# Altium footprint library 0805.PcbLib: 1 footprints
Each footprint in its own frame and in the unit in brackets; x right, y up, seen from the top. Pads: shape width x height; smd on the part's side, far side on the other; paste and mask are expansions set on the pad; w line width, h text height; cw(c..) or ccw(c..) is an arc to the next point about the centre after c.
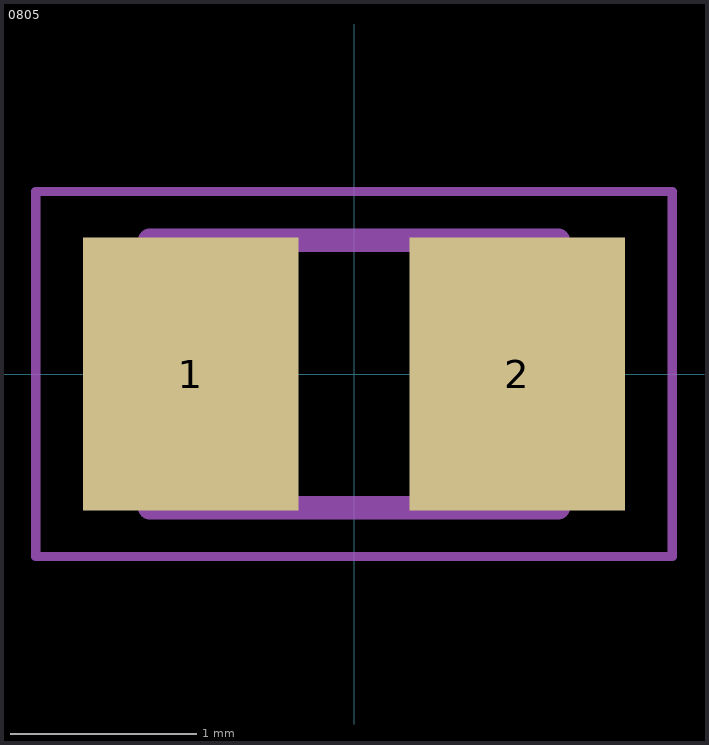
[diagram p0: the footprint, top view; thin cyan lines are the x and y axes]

## 0805 [mm]
pads (2):
  rect 1.16x1.47 smd: 1(-0.88,0) 2(0.88,0)
Assembly Top:
  lines w0.127: -1.1,-0.72 -1.1,0.72 1.1,0.72 1.1,-0.72 -1.1,-0.72
Courtyard Top:
  lines w0.05: -1.713,-0.983 -1.713,0.983 1.713,0.983 1.713,-0.983 -1.713,-0.983
3D body "step_temp.STEP": height 0.94, standoff 0, extent -1.005,-0.625 1.005,0.625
